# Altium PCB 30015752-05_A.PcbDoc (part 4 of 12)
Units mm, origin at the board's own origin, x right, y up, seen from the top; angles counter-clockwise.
Board outline 100.05 x 72 mm, 10 copper layers (Top, GND_2, Signal_3, Signal_4, PWR_5, GND_6, Signal_7, Signal_8, GND_9, Bottom), stack 1.493 mm thick; 577 components, 546 nets, 2389 pads, 1412 vias.
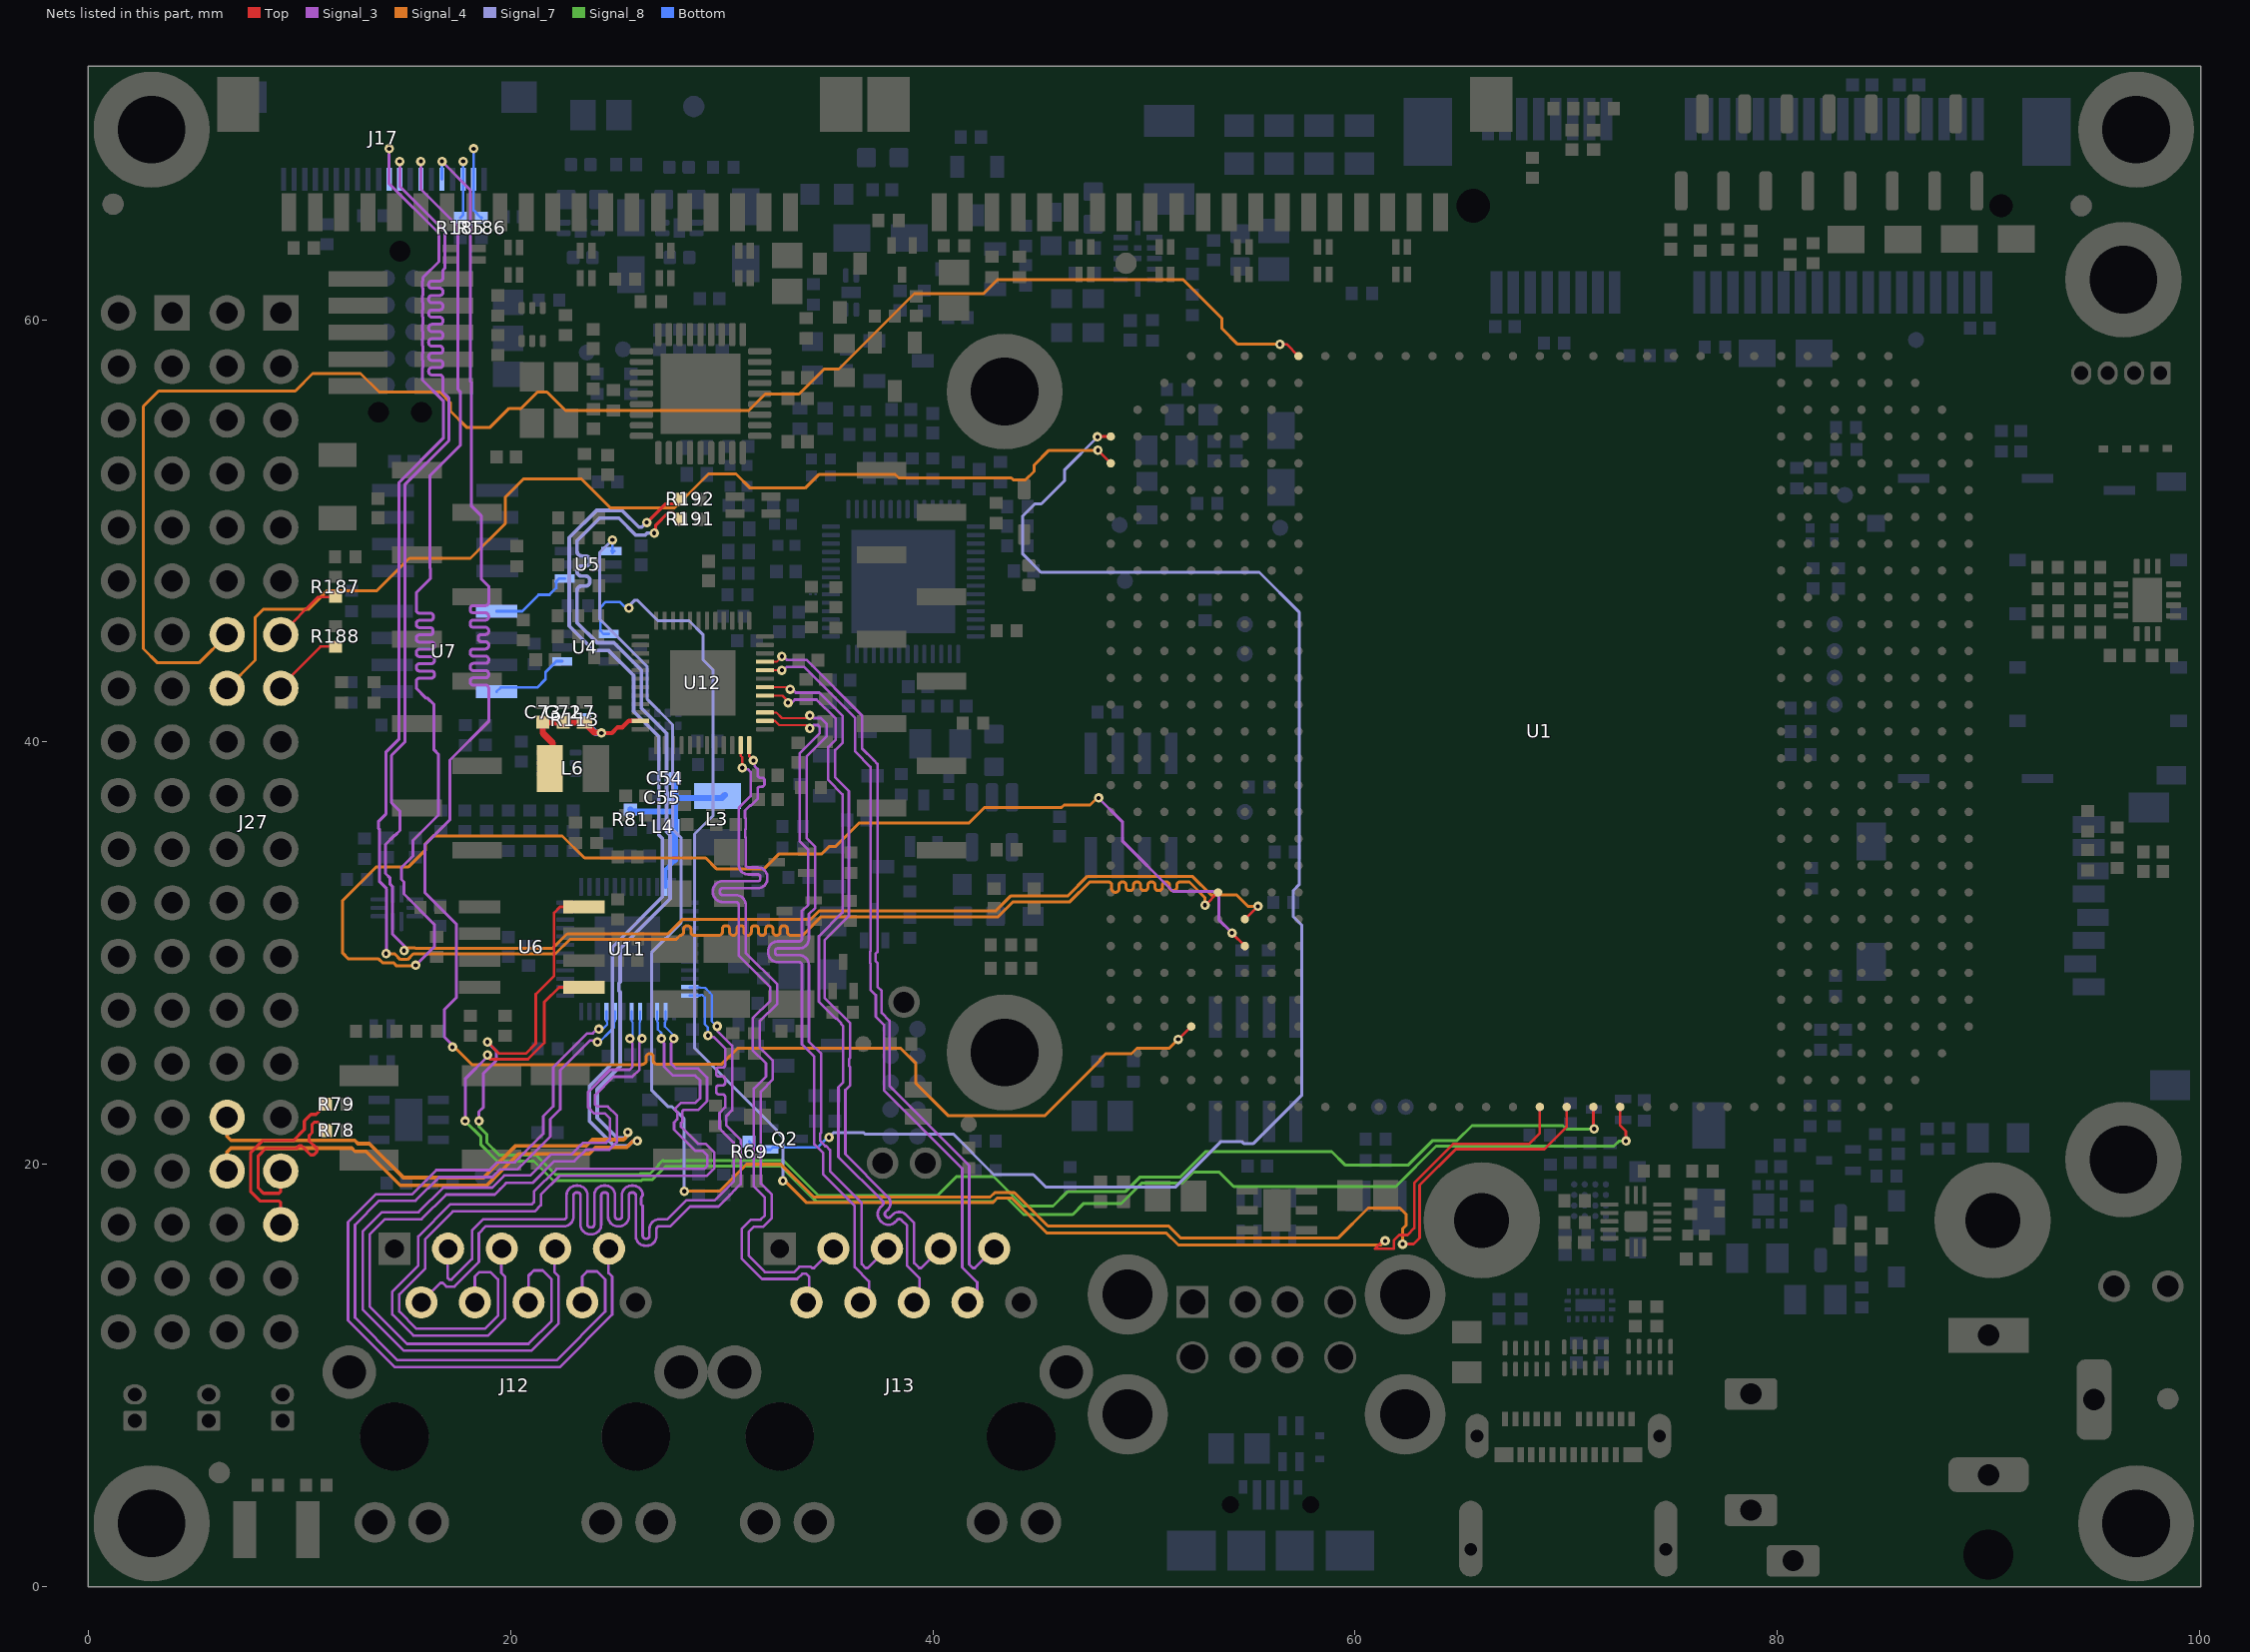
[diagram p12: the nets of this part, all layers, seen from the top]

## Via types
v1: diameter 0.45, hole 0.2, Top to Bottom, tented both sides, 1412 vias

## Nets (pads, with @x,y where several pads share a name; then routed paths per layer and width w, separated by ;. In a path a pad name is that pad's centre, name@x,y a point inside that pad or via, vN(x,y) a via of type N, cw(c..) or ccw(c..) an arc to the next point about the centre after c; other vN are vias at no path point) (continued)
CSI_MCLK: J17.11 U1.AJ21 | length 91.6
  Top w0.127: v1(52.89,32.27) 52.9,32.27 U1.AJ21@53.51,32.88
  Signal_3 w0.142: v1(14.101,29.976) 14.111,29.976 14.131,29.996 14.131,31.415 14.131,33.05 13.8,33.381 13.8,35.852 13.752,35.9 13.752,36.25 14.088,36.586 14.088,39.516 14.722,40.15 14.722,52.299 16.808,54.384 16.808,56.167 15.828,57.147 15.828,57.712 15.85,57.734 15.85,58.068 15.828,58.09 15.828,58.396 15.85,58.418 15.85,58.752 15.828,58.775 15.828,59.081 15.85,59.103 15.85,59.437 15.828,59.459 15.828,59.765 15.85,59.787 15.85,60.121 15.828,60.143 15.828,60.45 15.85,60.472 15.85,60.806 15.828,60.828 15.828,61.134 15.85,61.156 15.85,61.49 15.828,61.512 15.828,61.819 15.85,61.841 15.85,62 16.6,62.75 16.6,64.094 14.25,66.444 v1(14.25,68.1)
  Signal_4 w0.142: v1(14.101,29.976) 14.5,29.976 14.775,29.702 15.125,29.702 15.388,29.965 22.115,29.965 22.798,30.648 27.828,30.648 28.025,30.845 28.042,30.845 ccw(c28.042,30.999) 28.196,30.999 28.196,31.141 cw(c28.35,31.141) 28.35,31.295 28.384,31.295 cw(c28.384,31.141) 28.538,31.141 28.538,30.999 ccw(c28.692,30.999) 28.692,30.845 28.881,30.845 29.025,30.845 29.8,30.845 29.877,30.845 ccw(c29.877,30.999) 30.031,30.999 30.031,31.148 cw(c30.185,31.148) 30.185,31.302 30.22,31.302 cw(c30.22,31.148) 30.374,31.148 30.374,30.999 ccw(c30.528,30.999) 30.528,30.845 30.562,30.845 ccw(c30.562,30.999) 30.716,30.999 30.716,31.148 cw(c30.87,31.148) 30.87,31.302 30.904,31.302 cw(c30.904,31.148) 31.058,31.148 31.058,30.999 ccw(c31.212,30.999) 31.212,30.845 31.246,30.845 ccw(c31.246,30.999) 31.4,30.999 31.4,31.148 cw(c31.554,31.148) 31.554,31.302 31.589,31.302 cw(c31.589,31.148) 31.743,31.148 31.743,30.999 ccw(c31.897,30.999) 31.897,30.845 31.931,30.845 ccw(c31.931,30.999) 32.085,30.999 32.085,31.148 cw(c32.239,31.148) 32.239,31.302 32.273,31.302 cw(c32.273,31.148) 32.427,31.148 32.427,30.999 ccw(c32.581,30.999) 32.581,30.845 32.615,30.845 ccw(c32.615,30.999) 32.769,30.999 32.769,31.148 cw(c32.923,31.148) 32.923,31.302 32.958,31.302 cw(c32.958,31.148) 33.112,31.148 33.112,30.999 ccw(c33.266,30.999) 33.266,30.845 33.454,30.845 33.625,30.845 33.833,30.845 34.713,31.725 43.1,31.725 43.81,32.435 46.491,32.435 47.431,33.375 48.075,33.375 48.131,33.375 48.32,33.375 cw(c48.32,33.221) 48.474,33.221 48.474,33.04 ccw(c48.628,33.04) 48.628,32.886 48.662,32.886 ccw(c48.662,33.04) 48.816,33.04 48.816,33.221 cw(c48.97,33.221) 48.97,33.375 49.004,33.375 cw(c49.004,33.221) 49.158,33.221 49.158,33.116 ccw(c49.312,33.116) 49.312,32.962 49.346,32.962 ccw(c49.346,33.116) 49.5,33.116 49.5,33.221 cw(c49.654,33.221) 49.654,33.375 49.689,33.375 cw(c49.689,33.221) 49.843,33.221 49.843,33.116 ccw(c49.997,33.116) 49.997,32.962 50.031,32.962 ccw(c50.031,33.116) 50.185,33.116 50.185,33.221 cw(c50.339,33.221) 50.339,33.375 50.373,33.375 cw(c50.373,33.221) 50.527,33.221 50.527,33.116 ccw(c50.681,33.116) 50.681,32.962 50.715,32.962 ccw(c50.715,33.116) 50.869,33.116 50.869,33.221 cw(c51.023,33.221) 51.023,33.375 51.058,33.375 cw(c51.058,33.221) 51.212,33.221 51.212,33.116 ccw(c51.366,33.116) 51.366,32.962 51.4,32.962 ccw(c51.4,33.116) 51.554,33.116 51.554,33.221 cw(c51.708,33.221) 51.708,33.375 51.725,33.375 52.15,33.375 52.89,32.635 v1(52.89,32.27)
  Bottom w0.127: J17.11@14.25,66.65 v1(14.25,68.1)
CSI_PCLK: J17.12 U1.AH22 | length 92.3
  Top w0.127: U1.AH22@54.78,31.61 55.39,32.22 v1(55.4,32.22)
  Signal_3 w0.142: 14.4,31.304 14.4,30.919 15.001,30.319 14.951,30.269 v1(14.951,30.126) ; 14.4,31.304 14.4,33.162 14.295,33.267 14.295,33.555 14.069,33.781 14.069,35.148 14.513,35.592 14.537,35.592 14.76,35.815 14.76,36.724 14.357,37.127 14.357,39.366 14.991,40 14.991,52.187 17.077,54.273 17.077,56.3 16.797,56.58 16.797,57.15 16.797,57.234 ccw(c16.643,57.234) 16.643,57.388 16.273,57.388 cw(c16.273,57.542) 16.119,57.542 16.119,57.576 cw(c16.273,57.576) 16.273,57.73 16.643,57.73 ccw(c16.643,57.884) 16.797,57.884 16.797,57.918 ccw(c16.643,57.918) 16.643,58.072 16.273,58.072 cw(c16.273,58.226) 16.119,58.226 16.119,58.26 cw(c16.273,58.26) 16.273,58.414 16.643,58.414 ccw(c16.643,58.568) 16.797,58.568 16.797,58.602 ccw(c16.643,58.602) 16.643,58.756 16.273,58.756 cw(c16.273,58.91) 16.119,58.91 16.119,58.945 cw(c16.273,58.945) 16.273,59.099 16.643,59.099 ccw(c16.643,59.253) 16.797,59.253 16.797,59.287 ccw(c16.643,59.287) 16.643,59.441 16.273,59.441 cw(c16.273,59.595) 16.119,59.595 16.119,59.629 cw(c16.273,59.629) 16.273,59.783 16.643,59.783 ccw(c16.643,59.937) 16.797,59.937 16.797,59.971 ccw(c16.643,59.971) 16.643,60.125 16.273,60.125 cw(c16.273,60.279) 16.119,60.279 16.119,60.314 cw(c16.273,60.314) 16.273,60.468 16.643,60.468 ccw(c16.643,60.622) 16.797,60.622 16.797,60.656 ccw(c16.643,60.656) 16.643,60.81 16.273,60.81 cw(c16.273,60.964) 16.119,60.964 16.119,60.998 cw(c16.273,60.998) 16.273,61.152 16.643,61.152 ccw(c16.643,61.306) 16.797,61.306 16.797,61.34 ccw(c16.643,61.34) 16.643,61.494 16.273,61.494 cw(c16.273,61.648) 16.119,61.648 16.119,61.683 cw(c16.273,61.683) 16.273,61.837 16.643,61.837 ccw(c16.643,61.991) 16.797,61.991 16.797,62.179 16.797,62.35 16.881,62.434 16.881,64.194 14.75,66.325 v1(14.75,67.5)
  Signal_4 w0.142: v1(14.951,30.126) 15.08,30.256 15.467,30.256 15.489,30.234 21.992,30.234 22.675,30.917 27.456,30.917 28.131,31.593 30.169,31.593 30.172,31.59 30.185,31.59 30.185,31.594 ; 30.186,31.593 30.219,31.593 ; 30.22,31.594 30.22,31.59 30.233,31.59 30.236,31.593 30.854,31.593 30.856,31.59 30.87,31.59 30.87,31.594 ; 30.871,31.593 30.903,31.593 ; 30.904,31.594 30.904,31.59 30.918,31.59 30.92,31.593 31.538,31.593 31.541,31.59 31.554,31.59 31.554,31.594 ; 31.555,31.593 31.588,31.593 ; 31.589,31.594 31.589,31.59 31.602,31.59 31.605,31.593 32.223,31.593 32.225,31.59 32.239,31.59 32.239,31.594 ; 32.24,31.593 32.272,31.593 ; 32.273,31.594 32.273,31.59 32.287,31.59 32.289,31.593 32.907,31.593 32.91,31.59 32.923,31.59 32.923,31.594 ; 32.924,31.593 32.957,31.593 ; 32.958,31.594 32.958,31.59 32.971,31.59 32.974,31.593 34.2,31.593 34.602,31.994 42.969,31.994 43.679,32.704 46.379,32.704 47.319,33.644 52.289,33.644 53.178,32.755 54.395,32.755 54.93,32.22 v1(55.4,32.22)
  Bottom w0.127: J17.12@14.75,66.65 v1(14.75,67.5)
CSI_RESET: J17.16 U1.AK26 | length 94.2
  Top w0.127: v1(51.62,25.92) 51.63,25.92 U1.AK26@52.24,26.53
  Signal_3 w0.142: v1(16.75,67.5) 18.1,66.15 18.1,57.074 18.154,57.02 18.154,51.171 18.606,50.719 18.606,47.731 18.965,47.372 18.965,46.975 18.965,46.804 18.965,46.616 cw(c18.811,46.616) 18.811,46.462 18.238,46.462 ccw(c18.238,46.308) 18.084,46.308 18.084,46.273 ccw(c18.238,46.273) 18.238,46.119 18.811,46.119 cw(c18.811,45.965) 18.965,45.965 18.965,45.931 cw(c18.811,45.931) 18.811,45.777 18.238,45.777 ccw(c18.238,45.623) 18.084,45.623 18.084,45.589 ccw(c18.238,45.589) 18.238,45.435 18.811,45.435 cw(c18.811,45.281) 18.965,45.281 18.965,45.247 cw(c18.811,45.247) 18.811,45.093 18.621,45.093 ccw(c18.621,44.939) 18.467,44.939 18.467,44.904 ccw(c18.621,44.904) 18.621,44.75 18.811,44.75 cw(c18.811,44.596) 18.965,44.596 18.965,44.562 cw(c18.811,44.562) 18.811,44.408 18.238,44.408 ccw(c18.238,44.254) 18.084,44.254 18.084,44.22 ccw(c18.238,44.22) 18.238,44.066 18.811,44.066 cw(c18.811,43.912) 18.965,43.912 18.965,43.878 cw(c18.811,43.878) 18.811,43.724 18.238,43.724 ccw(c18.238,43.57) 18.084,43.57 18.084,43.535 ccw(c18.238,43.535) 18.238,43.381 18.811,43.381 cw(c18.811,43.227) 18.965,43.227 18.965,43.193 cw(c18.811,43.193) 18.811,43.039 18.238,43.039 ccw(c18.238,42.885) 18.084,42.885 18.084,42.851 ccw(c18.238,42.851) 18.238,42.697 18.811,42.697 cw(c18.811,42.543) 18.965,42.543 18.965,42.475 18.965,40.985 17.12,39.141 17.12,36.32 15.951,35.15 15.951,32.853 17.443,31.361 17.443,27.912 16.877,27.346 16.877,26.023 17.248,25.652 v1(17.248,25.548)
  Signal_4 w0.142: v1(17.248,25.548) 17.352,25.548 18.171,24.729 26.23,24.729 26.25,24.749 26.267,24.749 ccw(c26.267,24.903) 26.421,24.903 26.421,25.082 cw(c26.575,25.082) 26.575,25.236 26.609,25.236 cw(c26.609,25.082) 26.763,25.082 26.763,24.903 ccw(c26.917,24.903) 26.917,24.749 27.5,24.749 30.009,24.749 30.76,25.5 38.475,25.5 39.2,24.775 39.2,23.831 40.717,22.313 45.313,22.313 47.929,24.929 47.929,24.976 48.187,25.235 49.413,25.235 49.675,25.497 51.197,25.497 v1(51.62,25.92)
  Bottom w0.127: J17.16@16.75,66.65 v1(16.75,67.5)
CSI_SCL: J17.18 R185.2 | length 2.7
  Bottom w0.127: R185.2@17.625,64.83 17.75,64.955 J17.18@17.75,66.65 v1(17.75,67.5)
CSI_SDA: J17.19 R186.2 | length 3.4
  Bottom w0.127: v1(18.25,68.1) J17.19@18.25,66.65 18.25,65.179 18.599,64.83 R186.2@18.624,64.83
CSI_VSYNC: J17.14 U1.AH23 | length 106.4
  Top w0.127: v1(54.17,30.96) 54.17,30.95 U1.AH23@54.78,30.34
  Signal_3 w0.142: v1(15.501,29.426) 16.392,30.318 16.392,31.358 14.944,32.806 14.944,33.379 14.833,33.49 14.833,34.063 15.375,34.605 15.375,35.336 16.582,36.543 16.582,39.418 16.375,39.625 16.375,41.773 16.075,42.073 16.007,42.073 15.53,42.55 15.53,42.681 15.53,42.87 cw(c15.684,42.87) 15.684,43.024 16.241,43.024 ccw(c16.241,43.178) 16.395,43.178 16.395,43.212 ccw(c16.241,43.212) 16.241,43.366 15.684,43.366 cw(c15.684,43.52) 15.53,43.52 15.53,43.554 cw(c15.684,43.554) 15.684,43.708 16.241,43.708 ccw(c16.241,43.862) 16.395,43.862 16.395,43.896 ccw(c16.241,43.896) 16.241,44.05 15.684,44.05 cw(c15.684,44.204) 15.53,44.204 15.53,44.239 cw(c15.684,44.239) 15.684,44.393 16.241,44.393 ccw(c16.241,44.547) 16.395,44.547 16.395,44.581 ccw(c16.241,44.581) 16.241,44.735 15.684,44.735 cw(c15.684,44.889) 15.53,44.889 15.53,44.923 cw(c15.684,44.923) 15.684,45.077 16.178,45.077 ccw(c16.178,45.231) 16.332,45.231 16.332,45.265 ccw(c16.178,45.265) 16.178,45.419 15.684,45.419 cw(c15.684,45.573) 15.53,45.573 15.53,45.608 cw(c15.684,45.608) 15.684,45.762 16.194,45.762 ccw(c16.194,45.916) 16.348,45.916 16.348,45.95 ccw(c16.194,45.95) 16.194,46.104 15.684,46.104 cw(c15.684,46.258) 15.53,46.258 15.53,46.275 15.53,47.07 16.199,47.739 16.199,48.228 16.171,48.255 16.171,52.605 17.615,54.05 17.615,56.591 17.5,56.707 17.5,64.425 15.75,66.175 v1(15.75,67.5) ; v1(47.852,37.352) 48.975,36.229 48.975,35.325 51.375,32.925 53.3,32.925 53.537,32.688 53.537,31.592 v1(54.17,30.96)
  Signal_4 w0.142: v1(15.501,29.426) 15.469,29.394 14.606,29.394 14.45,29.55 13.929,29.55 13.754,29.725 12.325,29.725 12.05,30 12.05,32.498 13.626,34.074 15.149,34.074 15.975,34.9 15.975,35.2 16.331,35.556 22.452,35.556 23.5,34.508 29.241,34.508 29.748,34 32.019,34 32.725,34.706 34.742,34.706 35.087,35.05 35.4,35.05 36.525,36.175 41.725,36.175 42.444,36.894 46.093,36.894 46.219,37.02 47.445,37.02 47.777,37.352 v1(47.852,37.352)
  Bottom w0.127: J17.14@15.75,66.65 v1(15.75,67.5)
DVDDL1: C54.2 C55.2 L3.2 L4.2 R81.1 U11.47 | length 9.9
  Bottom w0.2: U11.47@27.34,33.142 27.34,33.965 27.78,34.405
  Bottom w0.3: R81.1@25.675,36.805 25.767,36.713 27.687,36.713 27.775,36.625 ; C55.2@27.76,37.35 C55.2@27.775,37.35 ; C54.2@27.775,38.225 C55.2@27.775,37.35 ; 27.78,34.405 27.78,35.85 27.775,35.855 27.775,36.625 ; L3.2@30.14,37.492 29.998,37.35 C55.2@27.775,37.35 ; 27.775,36.625 C55.2@27.775,37.35
DVDDL2: C72.2 C73.2 L6.2 L7.2 R113.1 U12.47 | length 8.5
  Top w0.2: v1(24.3,40.425) 24.8,40.425 25.075,40.7 25.3,40.7 25.6,41 U12.47@26.15,41
  Top w0.3: 21.525,40.425 C73.2@21.525,40.94 21.545,40.92 L7.2@23.5,40.92 23.97,40.45 v1@24.3,40.45 ; 21.55,40.4 22,39.95 L6.2@22,38.7
  Bottom w0.3: R113.1@23.525,40.945 23.551,40.945 23.648,40.848 23.648,40.826 24.049,40.425 v1(24.3,40.425)
ENET_PWR: Q2.G R69.2 U1.AN4 | length 74.8
  Top w0.127: v1(47.8,54.45) 47.82,54.47 U1.AN4@48.43,54.47
  Signal_7 w0.142: v1(35.08,21.28) 35.292,21.492 36.737,21.492 36.791,21.438 40.962,21.438 42.881,19.519 44.762,19.519 45.363,18.917 51.481,18.917 53.65,21.087 54.623,21.087 54.721,20.988 55.188,20.988 57.487,23.287 57.487,31.313 57.08,31.72 57.08,32.97 57.35,33.24 57.35,46.158 55.468,48.04 45.12,48.04 44.26,48.9 44.26,50.708 44.829,51.278 45.137,51.278 46.25,52.391 46.25,52.9 v1(47.8,54.45)
  Bottom w0.127: R69.2@31.3,21.08 31.521,20.859 31.966,20.859 32.125,20.7 Q2.G@32.31,20.7 32.419,20.81 34.56,20.81 35.03,21.28 v1(35.08,21.28)
ETH1_TXRXA_N: J12.3 U11.12 | length 39.8
  Signal_3 w0.124: J12.3@17.041,16.005 17.023,15.987 17.023,14.614 17.096,14.541 17.199,14.541 18.17,15.512 18.17,16.87 18.7,17.4 22.525,17.4 ccw(c22.525,17.529) 22.655,17.529 22.655,18.534 cw(c23.114,18.534) 23.114,18.993 23.18,18.993 cw(c23.18,18.534) 23.639,18.534 23.639,17.149 ccw(c23.769,17.149) 23.769,17.019 23.834,17.019 ccw(c23.834,17.149) 23.964,17.149 23.964,18.534 cw(c24.424,18.534) 24.424,18.993 24.489,18.993 cw(c24.489,18.534) 24.949,18.534 24.949,17.529 ccw(c25.078,17.529) 25.078,17.4 25.144,17.4 ccw(c25.144,17.529) 25.273,17.529 25.273,18.534 cw(c25.733,18.534) 25.733,18.993 25.798,18.993 cw(c25.798,18.534) 26.258,18.534 26.258,18.519 26.2,18.461 26.2,18.421 26.186,18.407 26.186,18.103 26.258,18.031 26.258,16.609 ccw(c26.388,16.609) 26.388,16.479 26.453,16.479 ccw(c26.453,16.609) 26.583,16.609 26.583,16.94 cw(c27.042,16.94) 27.042,17.4 27.433,17.4 28.333,18.3 28.444,18.3 28.446,18.301 29.676,18.301 30.57,19.195 30.57,21.03 30.068,21.532 29.895,21.705 29.895,22.431 30.164,22.701 30.164,23.05 30.164,23.188 ccw(c30.037,23.188) 30.037,23.315 29.865,23.315 cw(c29.865,23.442) 29.737,23.442 29.737,23.612 cw(c29.865,23.612) 29.865,23.739 30.037,23.739 ccw(c30.037,23.867) 30.164,23.867 30.164,24.037 ccw(c30.037,24.037) 30.037,24.164 29.865,24.164 cw(c29.865,24.291) 29.737,24.291 29.737,24.461 cw(c29.865,24.461) 29.865,24.588 30.037,24.588 ccw(c30.037,24.716) 30.164,24.716 30.164,25.013 30.164,25.225 30.164,25.49 29.616,26.038 29.412,26.038 v1(29.35,26.1)
  Bottom w0.102: U11.12@28.49,27.992 28.961,27.992 28.995,28.027 29.073,28.027 29.2,27.9 29.2,26.633 29.342,26.492 29.342,26.108 v1(29.35,26.1)
ETH1_TXRXA_P: J12.2 U11.11 | length 39.8
  Signal_3 w0.124: J12.2@15.771,13.465 16.686,14.381 16.79,14.381 16.959,14.211 17.336,14.211 18.5,15.375 18.5,16.733 18.837,17.07 22.525,17.07 ccw(c22.525,17.529) 22.985,17.529 22.985,18.534 cw(c23.114,18.534) 23.114,18.663 23.18,18.663 cw(c23.18,18.534) 23.309,18.534 23.309,17.149 ccw(c23.769,17.149) 23.769,16.689 23.834,16.689 ccw(c23.834,17.149) 24.294,17.149 24.294,18.534 cw(c24.424,18.534) 24.424,18.663 24.489,18.663 cw(c24.489,18.534) 24.619,18.534 24.619,17.529 ccw(c25.078,17.529) 25.078,17.07 25.144,17.07 ccw(c25.144,17.529) 25.603,17.529 25.603,18.534 cw(c25.733,18.534) 25.733,18.663 25.798,18.663 cw(c25.798,18.534) 25.928,18.534 25.928,16.609 ccw(c26.388,16.609) 26.388,16.149 26.453,16.149 ccw(c26.453,16.609) 26.913,16.609 26.913,16.94 cw(c27.042,16.94) 27.042,17.07 27.57,17.07 28.5,18 29.842,18 30.386,18.544 30.386,18.552 30.628,18.794 30.636,18.794 30.9,19.058 30.9,21.167 30.225,21.842 30.225,22.294 30.494,22.564 30.494,25.627 29.812,26.309 29.812,26.513 29.785,26.54 v1(29.78,26.54)
  Bottom w0.102: U11.11@28.49,28.392 28.961,28.392 28.995,28.357 29.21,28.357 29.433,28.133 29.53,28.037 29.53,26.77 29.76,26.54 v1(29.78,26.54)
ETH1_TXRXB_N: J12.5 U11.15 | length 39.7
  Signal_3 w0.124: J12.5@19.581,16.005 19.563,15.987 19.563,14.854 19.733,14.684 19.733,12.691 18.937,11.895 15.388,11.895 14.395,12.888 14.395,13.977 15.625,15.207 15.625,16.592 17.133,18.1 21,18.1 21.107,18.207 21.107,18.707 22.18,19.78 29.155,19.78 29.325,19.95 29.325,20.408 29.088,20.645 28.742,20.645 27.745,21.642 27.745,21.984 27.891,22.13 27.891,22.473 27.761,22.603 28.068,22.91 28.759,22.91 28.975,23.126 28.975,23.975 28.746,24.204 27.704,24.204 27.273,24.635 27.273,25.739 27.15,25.862 v1(27.15,25.95)
  Bottom w0.102: U11.15@26.94,27.242 26.94,26.771 26.975,26.736 26.975,26.383 27.15,26.208 v1(27.15,25.95)
ETH1_TXRXB_P: J12.4 U11.14 | length 39.6
  Signal_3 w0.124: J12.4@18.311,13.465 18.311,14.686 18.525,14.9 19.05,14.9 19.402,14.548 19.402,12.827 18.8,12.225 15.525,12.225 14.725,13.025 14.725,13.84 15.955,15.071 15.955,16.455 17.27,17.77 21.137,17.77 21.437,18.071 21.437,18.571 22.317,19.45 29.292,19.45 29.655,19.813 29.655,20.545 29.225,20.975 28.879,20.975 28.075,21.779 28.075,21.958 28.142,22.025 28.142,22.517 28.204,22.579 28.896,22.579 29.305,22.989 29.305,24.112 28.883,24.534 27.841,24.534 27.604,24.771 27.604,25.739 27.727,25.862 v1(27.727,25.95)
  Bottom w0.102: U11.14@27.34,27.242 27.34,26.771 27.305,26.736 27.305,26.52 27.727,26.098 v1(27.727,25.95)
ETH1_TXRXC_N: J12.7 U11.18 | length 39.8
  Signal_3 w0.124: J12.7@22.121,16.005 22.075,15.959 22.075,14.892 22.273,14.694 22.273,12.456 20.987,11.17 14.955,11.17 12.995,13.13 12.995,16.82 13.905,17.73 15.646,17.73 16.816,18.9 19.125,18.9 19.7,19.475 20.925,19.475 21.93,20.48 22.888,20.48 23.433,21.025 24.533,21.025 24.7,21.192 24.7,22.183 24.473,22.41 23.96,22.41 23.67,22.7 23.67,23.42 24.729,24.479 25.629,24.479 25.775,24.625 25.775,25.739 25.651,25.862 v1(25.651,25.95)
  Bottom w0.102: v1(25.651,25.95) 25.775,26.073 25.775,26.736 25.74,26.771 U11.18@25.74,27.242
ETH1_TXRXC_P: J12.6 U11.17 | length 39.8
  Signal_3 w0.124: 19.506,18.831 19.245,18.57 16.952,18.57 15.783,17.4 14.042,17.4 13.325,16.683 13.325,13.267 15.092,11.5 20.85,11.5 21.942,12.592 21.942,14.558 21.525,14.975 21.1,14.975 20.851,14.726 J12.6@20.851,13.465 ; 19.506,18.832 19.748,19.074 ; 19.749,19.074 19.8,19.125 21.042,19.125 22.067,20.15 23.025,20.15 23.575,20.7 24.675,20.7 25.03,21.055 25.03,22.32 24.61,22.74 24.097,22.74 24,22.837 24,23.283 24.866,24.149 25.766,24.149 26.105,24.488 26.105,25.739 26.228,25.862 v1(26.228,25.95)
  Bottom w0.102: U11.17@26.14,27.242 26.14,26.771 26.105,26.736 26.105,26.073 v1(26.228,25.95)
ETH1_TXRXD_N: J12.9 U11.21 | length 40.7
  Signal_3 w0.124: v1(24.18,26.4) 24.087,26.4 23.889,26.202 23.627,26.202 22.02,24.595 22.02,22.745 21.55,22.275 21.55,21.45 20.2,20.1 19.375,20.1 19.005,19.73 16.471,19.73 16.471,19.712 15.333,18.575 13.608,18.575 12.3,17.267 12.3,12.608 14.513,10.395 22.32,10.395 24.813,12.888 24.813,14.679 24.643,14.849 24.643,15.987 J12.9@24.661,16.005
  Bottom w0.102: v1(24.18,26.4) 24.2,26.4 v1@24.275,26.325 ; v1@24.275,26.325 24.575,26.625 24.575,26.736 24.54,26.771 U11.21@24.54,27.242
ETH1_TXRXD_P: J12.8 U11.20 | length 40.7
  Signal_3 w0.124: J12.8@23.391,13.465 23.391,14.691 23.625,14.925 24.1,14.925 24.482,14.543 24.482,13.024 22.183,10.725 14.65,10.725 12.63,12.745 12.63,17.13 13.775,18.275 15.5,18.275 16.625,19.4 19.142,19.4 19.512,19.77 20.337,19.77 21.88,21.313 21.88,22.138 22.35,22.608 22.35,24.458 23.763,25.871 23.889,25.871 24.012,25.748 24.064,25.8 v1(24.113,25.8)
  Bottom w0.102: v1(24.113,25.8) 24.165,25.748 24.742,26.325 24.905,26.488 24.905,26.736 24.94,26.771 U11.20@24.94,27.242
ETH2_TXRXA_N: J13.3 U12.12 | length 36
  Top w0.102: U12.12@31.3,39.85 31.3,39.417 31.305,39.412 31.305,39.32 v1(31.5,39.125)
  Signal_3 w0.124: v1(31.5,39.125) 31.562,39.063 31.562,38.859 31.7,38.721 31.7,38.525 31.7,38.44 ccw(c31.827,38.44) 31.827,38.313 31.9,38.313 cw(c31.9,38.185) 32.027,38.185 32.027,38.016 cw(c31.9,38.016) 31.9,37.888 31.827,37.888 ccw(c31.827,37.761) 31.7,37.761 31.7,37.725 31.7,37.309 31.385,36.994 31.348,36.994 31.106,36.752 31.106,36.408 31.133,36.381 31.133,35.869 31.111,35.847 31.111,35.503 31.133,35.481 31.133,34.192 ccw(c31.262,34.192) 31.262,34.063 31.704,34.063 cw(c31.704,33.603) 32.164,33.603 32.164,33.538 cw(c31.704,33.538) 31.704,33.078 30.045,33.078 ccw(c30.045,32.948) 29.916,32.948 29.916,32.883 ccw(c30.045,32.883) 30.045,32.753 30.673,32.753 cw(c30.673,32.294) 31.133,32.294 31.133,30.027 32.63,28.53 32.63,27.613 31.8,26.783 31.8,25.542 32.425,24.917 32.425,24.025 31.85,23.45 31.85,19.092 32.119,18.823 32.188,18.754 32.372,18.57 32.372,17.447 32.119,17.194 31.975,17.05 31.525,17.05 31.275,16.8 31.275,15.675 32.05,14.9 33.437,14.9 33.684,15.146 34.215,15.146 34.272,15.089 34.375,15.089 J13.3@35.291,16.005
ETH2_TXRXA_P: J13.2 U12.11 | length 36
  Top w0.102: U12.11@30.9,39.85 30.9,39.35 30.975,39.275 v1(30.975,38.775)
  Signal_3 w0.124: v1(30.975,38.775) 31.037,38.713 31.241,38.713 31.37,38.584 31.37,37.446 30.803,36.879 30.803,34.192 ccw(c31.262,34.192) 31.262,33.733 31.704,33.733 cw(c31.704,33.603) 31.834,33.603 31.834,33.538 cw(c31.704,33.538) 31.704,33.408 30.045,33.408 ccw(c30.045,32.948) 29.586,32.948 29.586,32.883 ccw(c30.045,32.883) 30.045,32.423 30.673,32.423 cw(c30.673,32.294) 30.803,32.294 30.803,29.89 32.3,28.393 32.3,27.75 31.47,26.92 31.47,25.405 32.095,24.78 32.095,24.162 31.52,23.587 31.52,18.955 32.042,18.433 32.042,17.584 31.838,17.38 31.388,17.38 30.945,16.937 30.945,15.538 31.913,14.57 33.574,14.57 33.82,14.816 34.009,14.816 34.15,14.675 34.15,13.594 J13.2@34.021,13.465
ETH2_TXRXB_N: J13.5 U12.15 | length 35
  Top w0.102: U12.15@32.05,41.4 32.588,41.4 32.858,41.13 34.027,41.13 34.148,41.252 v1(34.177,41.252)
  Signal_3 w0.124: v1(34.177,41.252) 34.237,41.252 34.238,41.254 34.361,41.13 34.701,41.13 34.967,40.864 34.967,40.267 34.031,39.331 34.031,35.436 34.43,35.037 34.43,32.155 34.13,31.855 34.13,30.688 cw(c33.671,30.688) 33.671,30.228 32.66,30.228 ccw(c32.66,30.098) 32.53,30.098 32.53,30.033 ccw(c32.66,30.033) 32.66,29.903 33.671,29.903 cw(c33.671,29.444) 34.13,29.444 34.13,26.384 34.13,25.817 34.718,25.229 34.718,21.504 34.666,21.452 34.666,21.108 34.908,20.866 34.948,20.866 35.13,20.684 35.13,19.67 36.63,18.17 36.63,15.271 36.812,15.089 36.915,15.089 J13.5@37.831,16.005
ETH2_TXRXB_P: J13.4 U12.14 | length 34.9
  Top w0.102: U12.14@32.05,41 32.521,41 32.721,40.8 34.027,40.8 v1(34.177,40.652) v1(34.177,40.652)
  Signal_3 w0.124: v1(34.177,40.652) 34.213,40.652 34.361,40.8 34.564,40.8 34.637,40.727 34.637,40.404 33.701,39.468 33.701,35.299 34.1,34.9 34.1,32.292 33.8,31.992 33.8,30.688 cw(c33.671,30.688) 33.671,30.558 32.66,30.558 ccw(c32.66,30.098) 32.2,30.098 32.2,30.033 ccw(c32.66,30.033) 32.66,29.573 33.671,29.573 cw(c33.671,29.444) 33.8,29.444 33.8,26.247 33.8,25.68 34.388,25.092 34.388,20.96 34.8,20.547 34.8,19.533 36.3,18.033 36.3,15.134 36.975,14.459 36.975,13.879 J13.4@36.561,13.465
ETH2_TXRXC_N: J13.7 U12.18 | length 35.7
  Top w0.102: U12.18@32.05,42.6 33.175,42.6 33.24,42.535 v1(33.24,42.5)
  Signal_3 w0.124: v1(33.24,42.5) 33.351,42.5 33.511,42.34 34.627,42.34 35.73,41.237 35.73,39.98 35.375,39.625 35.375,38.325 36.022,37.678 36.022,31.755 34.875,30.608 34.875,27.895 36.088,26.683 36.088,25.048 36.038,24.998 36.038,24.655 36.088,24.604 36.088,23.749 35.858,23.519 35.858,20.483 37.856,18.485 cw(c37.531,18.16) 37.99,18.16 cw(c37.531,18.16) 37.856,17.835 37.758,17.738 ccw(c37.85,17.646) 37.759,17.555 37.805,17.508 ccw(c37.896,17.6) 37.988,17.508 38.085,17.606 cw(c38.41,17.281) 38.735,17.606 39.112,17.229 39.112,15.329 39.352,15.089 39.455,15.089 J13.7@40.371,16.005
ETH2_TXRXC_P: J13.6 U12.17 | length 35.8
  Top w0.102: U12.17@32.05,42.2 32.875,42.2 33.14,41.935 v1(33.14,41.86)
  Signal_3 w0.124: v1(33.14,41.86) 33.291,41.86 33.301,41.85 33.461,42.01 34.49,42.01 35.4,41.1 35.4,40.125 35.045,39.77 35.045,38.205 35.725,37.525 35.725,31.925 34.603,30.803 34.603,27.701 35.389,26.914 35.422,26.914 35.664,26.672 35.664,26.639 35.758,26.546 35.758,23.886 35.528,23.656 35.528,20.346 37.622,18.252 cw(c37.531,18.16) 37.66,18.16 cw(c37.531,18.16) 37.622,18.069 37.525,17.971 ccw(c37.85,17.646) 37.525,17.321 37.571,17.275 ccw(c37.896,17.6) 38.221,17.275 38.319,17.372 cw(c38.41,17.281) 38.502,17.372 38.782,17.092 38.782,15.192 39.375,14.599 39.375,13.739 J13.6@39.101,13.465
ETH2_TXRXD_N: J13.9 U12.21 | length 35.7
  Top w0.102: U12.21@32.05,43.8 32.6,43.8 v1(32.85,44.05)
  Signal_3 w0.124: v1(32.85,44.05) 32.926,44.05 33.086,43.89 34.01,43.89 36.65,41.25 36.65,39.692 37.205,39.137 37.38,38.962 37.38,30.066 37.288,29.973 37.288,29.63 37.38,29.537 37.38,28.403 37.575,28.208 37.575,27.181 37.95,26.806 37.95,23.717 41.724,19.943 41.724,15.257 41.892,15.089 41.995,15.089 J13.9@42.911,16.005
ETH2_TXRXD_P: J13.8 U12.20 | length 35.6
  Top w0.102: U12.20@32.05,43.4 v1(32.85,43.4)
  Signal_3 w0.124: v1(32.85,43.4) 32.926,43.4 33.086,43.56 33.89,43.56 36.32,41.13 36.32,39.555 37.05,38.825 37.05,30.091 37.036,30.077 37.036,29.526 37.05,29.512 37.05,28.266 37.3,28.016 37.3,26.989 37.689,26.6 37.689,23.511 41.394,19.806 41.394,15.12 42.1,14.414 42.1,13.924 J13.8@41.641,13.465
EXP_I2C_GPIO: J27.16 U1.AN5 | length 50.8
  Top w0.127: v1(47.82,53.82) 47.82,53.81 U1.AN5@48.43,53.2
  Signal_4 w0.142: J27.16@6.56,42.54 7.9,43.88 7.9,45.9 8.3,46.3 10.45,46.3 11.325,47.175 13.675,47.175 15.2,48.7 18.1,48.7 19.75,50.35 19.75,51.6 20.623,52.473 23.35,52.473 24.729,51.094 27.769,51.094 29.373,52.698 30.677,52.698 31.35,52.025 33.95,52.025 34.594,52.669 38.225,52.669 38.388,52.506 43.72,52.506 43.815,52.41 44.389,52.41 44.795,52.816 44.795,53.114 45.501,53.82 v1(47.82,53.82)
EXP_I2C_IRQ_N: J27.14 U1.AF1 | length 78.3
  Top w0.127: v1(56.44,58.84) 56.76,58.84 U1.AF1@57.32,58.28
  Signal_4 w0.142: J27.14@6.575,45.085 5.24,43.75 3.275,43.75 2.6,44.425 2.6,55.9 3.325,56.625 9.8,56.625 10.625,57.45 12.897,57.45 13.774,56.573 16.65,56.573 17.15,56.073 17.15,55.675 17.916,54.909 19.034,54.909 19.929,55.804 20.506,55.804 21.275,56.573 21.725,56.573 22.598,55.7 31.276,55.7 32.064,56.488 33.667,56.488 34.848,57.669 35.548,57.669 39.118,61.238 42.398,61.238 43.05,61.89 51.869,61.89 52.295,61.465 52.295,61.461 53.697,60.059 53.697,59.584 54.441,58.84 v1(56.44,58.84)
EXP_I2C_SCL: J27.13 R187.2 | length 3.3
  Top w0.127: J27.13@9.1,45.08 10.89,46.87 R187.2@11.7,46.87
EXP_I2C_SDA: J27.15 R188.2 | length 3.5
  Top w0.127: J27.15@9.1,42.54 9.1,42.628 10.992,44.52 R188.2@11.7,44.52
EXPANSION_USB1_D_N: J27.34 R192.2 | length 62.8
  Top w0.15: v1(26.45,50.4) 27.325,51.275 27.82,51.275 R192.2@28.045,51.5
  Signal_4 w0.175: J27.34@6.56,19.68 6.56,19.685 6.56,20.576 6.75,20.766 12.467,20.766 12.615,20.617 13.158,20.617 14.768,19.007 18.878,19.007 20.371,20.5 23.721,20.5 24.028,20.807 25.503,20.807 25.797,21.101 v1(26.001,21.101)
  Signal_7 w0.175: v1(26.001,21.101) 25.98,21.101 25.965,21.085 25.781,21.085 25.578,20.882 24.897,20.882 23.732,22.047 23.732,23.707 24.819,24.794 24.819,30.294 27.188,32.663 27.188,35.436 27.025,35.598 27.025,40.254 25.825,41.454 25.825,43.15 24.643,44.332 23.947,44.332 22.782,45.497 22.782,49.678 24.079,50.975 25.275,50.975 26.075,50.175 26.225,50.175 v1(26.45,50.4)
EXPANSION_USB1_D_P: J27.32 R191.2 | length 62.9
  Top w0.15: v1(26.8,49.9) 26.877,49.977 26.877,50.277 27.475,50.875 27.72,50.875 R191.2@28.045,50.55
  Signal_4 w0.175: J27.32@6.56,22.22 6.56,21.324 6.75,21.134 12.619,21.134 12.768,20.985 13.31,20.985 14.921,19.375 18.725,19.375 20.218,20.868 23.568,20.868 23.875,21.175 25.35,21.175 25.55,21.375 v1(25.55,21.525)
  Signal_7 w0.175: v1(25.55,21.525) 25.55,21.375 25.425,21.25 25.05,21.25 24.1,22.2 24.1,23.554 25.187,24.642 25.187,28.166 25.135,28.218 25.135,28.582 25.187,28.634 25.187,30.212 27.556,32.581 27.556,35.588 27.393,35.751 27.393,40.407 26.193,41.607 26.193,43.407 24.9,44.7 24.1,44.7 23.15,45.65 23.15,46.95 23.15,47.173 cw(c23.364,47.173) 23.364,47.387 23.541,47.387 ccw(c23.541,47.6) 23.755,47.6 23.755,47.648 ccw(c23.541,47.648) 23.541,47.862 23.364,47.862 cw(c23.364,48.076) 23.15,48.076 23.15,48.123 cw(c23.364,48.123) 23.364,48.337 23.541,48.337 ccw(c23.541,48.551) 23.755,48.551 23.755,48.599 ccw(c23.541,48.599) 23.541,48.812 23.364,48.812 cw(c23.364,49.026) 23.15,49.026 23.15,49.05 23.15,49.525 24.225,50.6 25.129,50.6 25.922,49.807 26.378,49.807 26.471,49.9 v1(26.8,49.9)
EXPANSION_USB2_D_N: J27.35 R79.2 | length 9.3
  Top w0.15: J27.35@9.1,17.14 9.1,17.145 9.1,18.2 9.043,18.257 8.147,18.257 7.682,18.722 7.682,20.553 8.247,21.118 9.697,21.118 10.232,21.653 10.232,22.053 10.547,22.368 10.788,22.368 R79.2@11.27,22.85
EXPANSION_USB2_D_P: J27.33 R78.2 | length 9.3
  Top w0.15: J27.33@9.1,19.68 9.1,18.7 9.025,18.625 8.3,18.625 8.05,18.875 8.05,20.4 8.4,20.75 9.85,20.75 9.975,20.875 10.1,20.875 10.525,20.45 10.675,20.45 10.825,20.6 10.825,20.75 10.45,21.125 10.45,21.35 10.6,21.5 10.6,21.9 10.7,22 10.87,22 R78.2@11.27,21.6
FLEXCAN1_RX: U1.R29 U6.4 | length 74.5
  Top w0.127: v1(18.9,25.8) 19.456,25.244 20.712,25.244 21.191,25.723 21.191,28.06 22.06,28.929 22.06,31.915 22.34,32.195 U6.4@23.47,32.195 ; U1.R29@71.29,22.72 71.29,21.71 v1(71.325,21.675)
  Signal_3 w0.142: v1(18.5,22.05) 18.5,22.494 18.719,22.713 18.719,24.321 19.324,24.926 19.324,25.372 18.9,25.797 v1(18.9,25.8)
  Signal_8 w0.142: v1(18.5,22.05) 18.5,21.795 18.872,21.423 18.872,21.031 19.476,20.427 21.213,20.427 22.134,19.506 26.09,19.506 26.142,19.558 26.612,19.558 27.017,19.963 27.017,20.009 27.186,20.178 27.239,20.178 27.253,20.164 28.05,20.164 28.063,20.178 32.925,20.178 34.578,18.525 40.217,18.525 41.115,19.423 42.883,19.423 44.281,18.025 45.702,18.025 46.377,18.7 49.111,18.7 49.799,19.388 51.708,19.388 52.922,20.603 58.898,20.603 59.525,19.976 62.526,19.976 63.68,21.13 64.83,21.13 65.538,21.838 69.841,21.838 70.004,21.675 v1(71.325,21.675)
FLEXCAN1_TX: U1.P29 U6.1 | length 72.3
  Top w0.127: v1(18.901,25.176) 18.901,25.099 19.025,24.975 20.822,24.975 21.6,25.753 21.6,27.687 22.298,28.385 U6.1@23.47,28.385 ; U1.P29@72.56,22.72 72.56,21.84 72.829,21.571 v1(72.829,21.101)
  Signal_3 w0.142: v1(17.85,22.05) 17.85,24.05 18.901,25.101 v1(18.901,25.176)
  Signal_8 w0.142: v1(17.85,22.05) 18.603,21.297 18.603,20.92 19.365,20.158 21.102,20.158 22.023,19.237 26.202,19.237 26.253,19.288 26.723,19.288 27.33,19.895 28.161,19.895 28.175,19.909 32.814,19.909 34.478,18.245 42.898,18.245 43.052,18.399 43.526,18.399 44.3,17.625 46.625,17.625 47.15,18.15 48.941,18.15 49.911,19.119 51.819,19.119 52.338,19.637 53.563,19.637 54.247,18.953 61.928,18.953 63.836,20.861 72.261,20.861 72.501,21.101 v1(72.829,21.101)
FLEXCAN2_RX: U4.1 U7.4 | length 3.9
  Bottom w0.127: U7.4@19.329,42.386 19.528,42.584 21.272,42.584 21.655,42.968 21.655,43.305 22.175,43.825 U4.1@22.45,43.825
FLEXCAN2_RX/UART3_RX: U1.U29 U4.4 | length 79.2
  Top w0.127: v1(61.425,16.375) 61.319,16.375 60.953,16.009 61.841,16.009 61.841,16.051 61.838,16.054 61.838,16.398 62.095,16.655 62.487,16.655 62.805,16.974 62.805,19.115 64.666,20.975 68.25,20.975 68.75,21.475 U1.U29@68.75,22.72
  Signal_4 w0.142: v1(32.9,19.22) 32.98,19.22 34.02,18.18 42.832,18.18 43.052,18.399 43.747,18.399 45.396,16.75 51.056,16.75 51.631,16.175 61.225,16.175 v1(61.425,16.375)
  Signal_7 w0.142: v1(25.601,46.352) 25.601,46.441 25.885,46.725 26,46.725 26.975,45.75 28.45,45.75 29.125,45.075 29.125,43.875 29.6,43.4 29.6,36.525 28.72,35.645 28.72,25.505 32.603,21.622 32.603,21.576 32.851,21.328 32.897,21.328 32.9,21.325 v1(32.9,19.22)
  Bottom w0.127: U4.4@24.65,45.125 24.396,45.125 24.259,45.262 24.259,46.387 24.508,46.635 25.177,46.635 25.46,46.352 v1(25.601,46.352)
FLEXCAN2_TX: U5.1 U7.1 | length 4.1
  Bottom w0.127: U7.1@19.329,46.196 20.546,46.196 21.325,46.975 21.838,46.975 22.163,47.3 22.163,47.613 22.3,47.75 U5.1@22.575,47.75
FLEXCAN2_TX/UART3_TX: U1.T29 U5.4 | length 85.9
  Top w0.127: v1(62.253,16.226) 62.776,16.226 63.059,16.509 63.059,19.009 64.771,20.721 68.971,20.721 70.02,21.77 U1.T29@70.02,22.72
  Signal_4 w0.142: v1(28.225,18.725) 29.9,18.725 31.175,20 32.798,20 34.349,18.449 42.721,18.449 42.94,18.668 43.858,18.668 45.452,17.075 51.175,17.075 51.75,16.5 59.189,16.5 60.619,17.931 62.119,17.931 62.424,17.625 62.424,17.125 62.25,16.951 62.253,16.948 v1(62.253,16.226)
  Signal_7 w0.142: v1(24.825,49.575) 24.225,48.975 24.225,45.825 26.479,43.571 26.479,42.021 27.679,40.821 27.679,35.869 28.075,35.473 28.075,31.425 26.675,30.025 26.675,23.52 27.471,22.724 27.652,22.724 28.225,22.151 v1(28.225,18.725)
  Bottom w0.127: U5.4@24.775,49.05 U5.4@24.825,49.05 ; v1(24.825,49.575) U5.4@24.825,49.05 ; U5.4@24.825,49.05 24.914,49.05 24.844,48.981 24.825,48.962 U5.4@24.825,49.05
